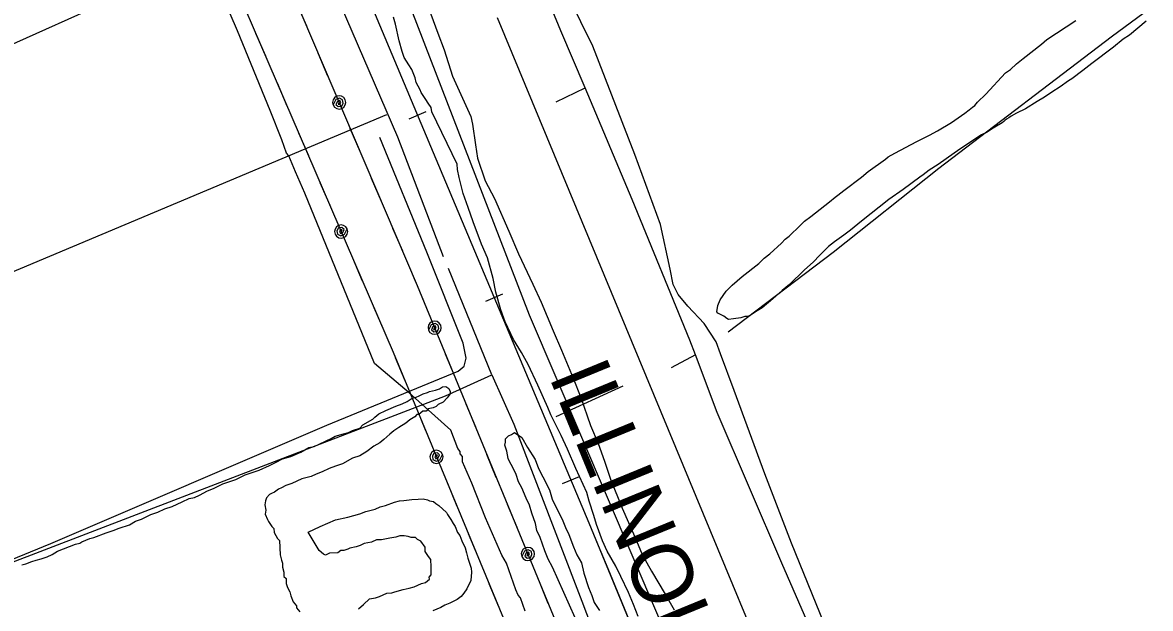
# Model space of a CAD drawing. Extents: x 3329297 to 3367176, y 649250 to 674653.
# Drawn here: x 3341368 to 3342909, y 669834 to 670634 of the extents above; entities that cross this region are included whole.
import ezdxf

# ---------------------------------------------------------------- set-up
doc = ezdxf.new("R2010")
doc.units = 0
for name, color, linetype in [('V-DTCH-CNTR', 7, 'Continuous'), ('V-RAIL-IDEN', 7, 'Continuous'), ('V-RAIL-TRAK', 7, 'Continuous'), ('V-ROAD-CNTR', 7, 'Continuous'), ('V-SITE-VEGE', 7, 'Continuous'), ('V-TOPO-SHOR', 7, 'Continuous'), ('V-UTIL-LINE', 7, 'Continuous')]:
    doc.layers.add(name, color=color, linetype=linetype)

msp = doc.modelspace()

# ---------------------------------------------------------------- linework, layer by layer
at = {"layer": 'V-DTCH-CNTR'}
for points in [[(3342681.3, 669387.6), (3342641.9, 669461.5), (3342593.9, 669531.2), (3342566.9, 669571.5), (3342550.7, 669601.8), (3342508.6, 669701.9), (3342418.3, 669923.3), (3342382, 670018), (3342340.3, 670131.6), (3342321.7, 670181.7), (3342315.5, 670198.2), (3342299.4, 670223), (3342277.1, 670246.7), (3342263.7, 670262.9), (3342256.9, 670276.2), (3342252.8, 670297.5), (3342239.4, 670358.1), (3342204.7, 670453.7), (3342147.3, 670601.7), (3342114.6, 670668.7)], [(3340890.2, 669711.6), (3341407, 669923.1), (3341783.9, 670084.3), (3341963.1, 670158.2), (3341971.5, 670164.8), (3341974.3, 670176), (3341970.3, 670196.3), (3341920.6, 670320.5), (3341856.2, 670477.1)]]:
    msp.add_lwpolyline(points, dxfattribs=at)
at = {"layer": 'V-RAIL-TRAK'}
for points in [[(3342142.3, 669950.7), (3341846.6, 670653.1)], [(3345872.4, 660898.3), (3345202.6, 662524.8), (3345202.6, 662524.8), (3343834.7, 665839), (3343834.7, 665839.1), (3342962.1, 667964.3), (3342962.1, 667964.3), (3342142.3, 669950.7), (3342142.3, 669950.7), (3341846.6, 670653.1)], [(3341896.4, 670502.6), (3341919.5, 670512.3)], [(3342001.2, 670253.8), (3342024.2, 670263.5)], [(3342105.9, 670004.9), (3342129, 670014.6)]]:
    msp.add_lwpolyline(points, dxfattribs=at)
msp.add_arc((2259538.4, 221964.1), 1171632.7, 22.3749135, 22.4799996, dxfattribs=at)
at = {"layer": 'V-ROAD-CNTR'}
msp.add_lwpolyline([(3342677.7, 669050.1), (3342017, 670640.3)], dxfattribs=at)
at = {"layer": 'V-SITE-VEGE'}
for points in [[(3341922.6, 670653.8), (3341935.4, 670619.4), (3341944.1, 670596.8), (3341955.7, 670560.6), (3341980.7, 670505.5), (3341982.9, 670495.4), (3341987, 670467.2), (3341989.5, 670448.7), (3342000.3, 670417.8), (3342012.7, 670393.6), (3342032.5, 670349.2), (3342045.7, 670318.4), (3342065.4, 670277), (3342076.6, 670252.2), (3342093.1, 670213.1), (3342104.4, 670187), (3342120.3, 670148.5), (3342130.9, 670122.4), (3342143.9, 670083.8), (3342154.4, 670059.5), (3342163.2, 670035.2), (3342171.4, 670010.8), (3342187.4, 669971.1), (3342204.5, 669932), (3342214.5, 669907.7), (3342227.4, 669885.4), (3342246.1, 669853.6), (3342258.3, 669832.4)], [(3341877.7, 670631.6), (3341874.9, 670641.1)], [(3342209.3, 669823.3), (3342202.7, 669839.9), (3342196, 669855.9), (3342185.5, 669877.7), (3342178.4, 669891.9), (3342166.7, 669912.5), (3342160.2, 669926.7), (3342152.1, 669948.7), (3342148.6, 669961.2), (3342142.4, 669980.8), (3342139, 669992.7), (3342123.9, 670025.2), (3342112.6, 670051.9), (3342104.1, 670070.2), (3342089.7, 670098.6), (3342085.7, 670108.7), (3342071.9, 670138.8), (3342058.8, 670167.2), (3342049.7, 670183.7), (3342038.8, 670201.4), (3342027.6, 670225.6), (3342021.6, 670241.6), (3342014.6, 670266), (3342010.9, 670284.6), (3342003.2, 670312.6), (3341995.2, 670331.5), (3341983.8, 670361.8), (3341977.1, 670381.4), (3341970.3, 670400.4), (3341964.6, 670422.4), (3341962.4, 670433.2), (3341962.1, 670440.4), (3341927.5, 670511.9), (3341926.6, 670517.9), (3341922.2, 670523.7), (3341919, 670529), (3341912.6, 670538.4), (3341911.3, 670542), (3341906.1, 670552), (3341904.6, 670558.6), (3341900, 670569.8), (3341896.1, 670576.3), (3341889.7, 670586.3), (3341887, 670594.6), (3341882.8, 670608.9), (3341877.7, 670631.6)], [(3342902.7, 670635.6), (3342880.1, 670616.8), (3342871.7, 670611), (3342858.1, 670600.4), (3342828.6, 670578.2), (3342816.5, 670568.4), (3342801.3, 670556.9), (3342796.8, 670554.4), (3342785.4, 670546.2), (3342774, 670538.7), (3342764.1, 670532.1), (3342754.2, 670526.2), (3342738.2, 670516.3), (3342726, 670510.4), (3342718.4, 670506.2), (3342715.3, 670503.7), (3342712.3, 670502), (3342710, 670500.4), (3342708.5, 670498.8), (3342706.2, 670497.1), (3342696.3, 670491.3), (3342694.1, 670489.6), (3342684.9, 670483.8), (3342678.1, 670480.5), (3342667.4, 670473.8), (3342659.1, 670468), (3342649.9, 670462.2), (3342640.8, 670455.6), (3342618.8, 670440), (3342606.7, 670432.5), (3342598.4, 670425.9), (3342593.8, 670422.7), (3342571.1, 670406.2), (3342551.3, 670392.2), (3342514.3, 670362.7), (3342499.2, 670350.4), (3342490.1, 670343.8), (3342477.2, 670334.8), (3342468.9, 670328.2), (3342456.9, 670316.1), (3342448.7, 670307.2), (3342435.8, 670295.8), (3342415.6, 670276.3), (3342405.8, 670268.1), (3342392.9, 670256.7), (3342378.6, 670244.5), (3342371.8, 670240.3), (3342362.6, 670234.5), (3342358.8, 670232.8), (3342354.9, 670232.7), (3342349.5, 670230.9), (3342339.4, 670229.7), (3342332.5, 670228.7), (3342330.1, 670230.1), (3342326.1, 670233.1), (3342318.1, 670237.5), (3342316.5, 670239), (3342317.7, 670247.6), (3342321.3, 670255.5), (3342329.4, 670267.5), (3342337.7, 670275.6), (3342351.3, 670287.1), (3342373.9, 670305.1), (3342381.4, 670312.4), (3342389, 670318.1), (3342404.8, 670332.8), (3342410, 670338.4), (3342415.3, 670342.5), (3342430.4, 670357.1), (3342436.4, 670362.8), (3342444.7, 670369.4), (3342470.4, 670389.1), (3342478, 670395.6), (3342481.8, 670398.1), (3342490.1, 670404.6), (3342514.3, 670422.7), (3342523.4, 670430.8), (3342546.9, 670447.3), (3342550.6, 670450.6), (3342559.8, 670455.6)], [(3342559.8, 670455.6), (3342589.6, 670471.6), (3342607.2, 670480.1), (3342617.9, 670485.9), (3342636.9, 670497.6), (3342655.1, 670510), (3342661.1, 670514.9), (3342665.7, 670518.2), (3342668.7, 670520.6), (3342672.4, 670525.4), (3342683.7, 670536), (3342710.6, 670565.1), (3342717.5, 670570), (3342725.7, 670577.4), (3342734.8, 670584.7), (3342759.8, 670604.4), (3342767.3, 670610.9), (3342806.8, 670636.6)], [(3341367.3, 669893.7), (3341372.9, 669895.3), (3341381.2, 669898.5), (3341386.8, 669900.1), (3341393.8, 669901.8), (3341402.1, 669904.9), (3341409, 669908), (3341415.9, 669912.5), (3341440.8, 669921.9), (3341446.4, 669923.5), (3341449.2, 669925), (3341460.2, 669929.7), (3341465.8, 669931.3), (3341482.5, 669937.5), (3341492.2, 669940.7), (3341500.5, 669943.9), (3341514.4, 669948.6), (3341522.7, 669953.2), (3341531, 669956.3), (3341543.4, 669962.4), (3341553.2, 669965.6), (3341562.8, 669970.2), (3341572.6, 669973.4), (3341586.4, 669979.6), (3341596.1, 669984.2), (3341603, 669985.8), (3341610, 669988.9), (3341621, 669995), (3341629.3, 669998.1), (3341641.7, 670004.2), (3341651.5, 670007.4), (3341659.8, 670010.5), (3341672.2, 670016.7), (3341682, 670019.8), (3341691.7, 670023), (3341705.5, 670029.2), (3341713.8, 670033.7), (3341723.5, 670038.3), (3341734.6, 670041.6), (3341748.4, 670047.7), (3341759.5, 670053.8), (3341766.4, 670055.5), (3341773.4, 670058.6), (3341783, 670063.2), (3341789.9, 670066.2), (3341795.5, 670069.3), (3341806.6, 670072.5), (3341813.6, 670074.2), (3341819.1, 670077.2), (3341828.8, 670080.4), (3341832.9, 670084.8), (3341846.6, 670092.4), (3341849.3, 670095.3), (3341854.8, 670099.7), (3341864.5, 670104.3), (3341878.3, 670110.5), (3341886.6, 670113.6), (3341893.6, 670116.7), (3341900.4, 670121.2), (3341906, 670122.8), (3341910.2, 670124.4), (3341915.7, 670127.4), (3341921.2, 670129), (3341924, 670130.5), (3341932.4, 670132.3), (3341937.9, 670133.9), (3341942, 670136.9), (3341946.3, 670137), (3341950.6, 670134.4), (3341952.2, 670130.2), (3341952.3, 670127.4), (3341948.3, 670121.6), (3341942.9, 670115.8)], [(3341942.9, 670115.8), (3341935.9, 670112.7), (3341933.2, 670109.8), (3341929.1, 670108.2), (3341922.1, 670106.5), (3341919.4, 670103.6), (3341915.2, 670103.4), (3341909.7, 670099), (3341906.9, 670098.9), (3341904.2, 670096), (3341897.3, 670091.5), (3341891.9, 670087.1), (3341882.3, 670081.1), (3341875.4, 670076.6), (3341869.9, 670072.1), (3341861.8, 670064.8), (3341856.3, 670060.4), (3341848.1, 670055.8), (3341838.5, 670048.4), (3341828.9, 670042.4), (3341819.1, 670039.2), (3341805.4, 670031.6), (3341795.6, 670028.5), (3341787.3, 670025.3), (3341777.6, 670020.7), (3341769.3, 670017.6), (3341762.4, 670014.5), (3341749.9, 670011.2), (3341736, 670005), (3341727.7, 670001.9), (3341722.2, 669998.9), (3341718, 669997.3), (3341712.6, 669992.9), (3341708.4, 669991.3), (3341705.6, 669989.8), (3341701.6, 669985.4), (3341700.3, 669981.1), (3341699.2, 669975.5), (3341700.8, 669968.5), (3341699.6, 669962.8), (3341702.7, 669955.9), (3341704.2, 669953.1), (3341708.7, 669946.3), (3341711.6, 669943.6), (3341711.9, 669938), (3341716.4, 669929.7), (3341719.3, 669927), (3341720.1, 669907.3), (3341721.8, 669900.3), (3341723.3, 669896.2), (3341723.5, 669890.6), (3341725.2, 669883.6), (3341725.4, 669878), (3341728.4, 669875.3), (3341728.6, 669868.2), (3341730.3, 669862.7), (3341733.3, 669857.2), (3341734.9, 669851.6), (3341738, 669843.3), (3341742.5, 669837.8), (3341742.6, 669835), (3341747, 669829.5)], [(3342123.1, 669821.5), (3342107.7, 669856.1), (3342092.3, 669890.7), (3342086.2, 669901.7), (3342081.6, 669912.8), (3342075.3, 669930.9), (3342070.7, 669940.6), (3342068.9, 669950.3), (3342064.1, 669964.2), (3342060.9, 669975.4), (3342056.3, 669985), (3342050.1, 669998.9), (3342045.6, 670007.1), (3342042.4, 670016.9), (3342037.8, 670026.5), (3342033.2, 670034.8), (3342031.7, 670039), (3342029.9, 670048.8), (3342026.8, 670057.1), (3342028, 670061.4), (3342027.8, 670065.6), (3342031.9, 670070), (3342036, 670071.5), (3342040.2, 670074.5), (3342050.3, 670067.8), (3342057.8, 670054.1), (3342068.3, 670037.6), (3342073, 670025.1), (3342079.1, 670014.1), (3342088.2, 669996.1), (3342091.5, 669983.6), (3342096.1, 669973.9), (3342105.3, 669956), (3342109.9, 669944.9), (3342114.5, 669935.2), (3342120.8, 669918.6), (3342125.4, 669907.5), (3342131.5, 669896.5), (3342134.8, 669882.5), (3342141.2, 669863.1), (3342145.9, 669852), (3342149.1, 669842.2), (3342156.5, 669831.3)], [(3341895, 669932.4), (3341889.4, 669933.6), (3341883.8, 669933.3), (3341878.2, 669931.7), (3341869.8, 669930), (3341858.6, 669928.1), (3341851.6, 669927.9), (3341844.7, 669924.8), (3341834.9, 669923), (3341829.4, 669920), (3341823.8, 669918.4), (3341815.4, 669916.6), (3341812.7, 669915.1), (3341807.1, 669913.5), (3341802.9, 669913.3), (3341798.8, 669910.4), (3341787.5, 669909.9), (3341782, 669906.9), (3341779.2, 669908.2), (3341773.3, 669913.6), (3341758.3, 669938.3), (3341774.9, 669946), (3341795.6, 669955.3), (3341812.4, 669958.7), (3341829.1, 669963.6), (3341837.4, 669966.7), (3341850, 669970), (3341856.9, 669973.1), (3341863.9, 669974.8), (3341876.3, 669979.5), (3341883.3, 669981.2), (3341888.9, 669981.4), (3341900.1, 669983.2), (3341908.6, 669983.6), (3341915.6, 669983.8), (3341921.3, 669982.6), (3341924.1, 669981.3), (3341929.8, 669980.2), (3341932.7, 669977.5), (3341937, 669974.8), (3341947.3, 669965.3), (3341948.8, 669962.6), (3341953.3, 669955.7), (3341956.3, 669950.2), (3341959.3, 669946.1), (3341962.4, 669937.8), (3341965.4, 669933.7), (3341968.5, 669926.8), (3341973, 669917.1), (3341974.7, 669910.1), (3341976.4, 669903.1), (3341979.6, 669893.4), (3341981.2, 669889.2), (3341981.4, 669883.6), (3341980.4, 669872.3), (3341975.2, 669860.9), (3341971.2, 669855.1), (3341967.2, 669850.7), (3341961.7, 669846.3), (3341952, 669841.7), (3341945.1, 669838.6), (3341939.6, 669835.6), (3341928.5, 669830.9)], [(3341918.3, 669912.2), (3341918.1, 669917.8), (3341912.2, 669926), (3341907.9, 669928.6), (3341904.9, 669931.3), (3341899.3, 669931.1), (3341895, 669932.4)], [(3341827.1, 669834), (3341833.9, 669839.9), (3341842, 669847.3), (3341850.4, 669849), (3341856, 669850.6), (3341865.7, 669855.2), (3341872.7, 669855.5), (3341876.8, 669857.1), (3341888, 669860.3), (3341896.4, 669862), (3341903.3, 669863.7), (3341913, 669868.3), (3341918.6, 669869.9), (3341924, 669874.4), (3341923.9, 669877.2), (3341926.6, 669880.1), (3341926.4, 669887.1), (3341926.2, 669891.3), (3341925.8, 669901.2), (3341922.8, 669905.3), (3341918.3, 669912.2)]]:
    msp.add_lwpolyline(points, dxfattribs=at)
at = {"layer": 'V-TOPO-SHOR'}
for p, q in [((3340278, 670120.4), (3341747.2, 670781)), ((3342097.3, 670525.9), (3342136.6, 670544.7)), ((3341025.8, 670155.5), (3341865.8, 670508.5)), ((3342287.5, 670180.5), (3342254, 670162.5)), ((3342188.1, 670137.7), (3342096.6, 670096))]:
    msp.add_line(p, q, dxfattribs=at)
for points in [[(3342332.2, 670211.6), (3342475.2, 670320.6), (3342619.6, 670435.2), (3342855.3, 670614.5), (3343080.5, 670780.8), (3343310, 670956), (3343491.2, 671086.3), (3343655.8, 671203.9), (3343697.2, 671233.5), (3343924, 671417.3), (3344230.2, 671648), (3344409.2, 671782.5), (3344486.9, 671840.9), (3344733.6, 672026.3), (3344845.9, 672104.6)], [(3342400.8, 669442.2), (3342272.5, 669740), (3342060.5, 670234.6), (3341844.7, 670793.1), (3341784.2, 670908.3), (3341727.2, 671023.5), (3341688, 671110.4), (3341661.3, 671167.1), (3341629.2, 671229.2)], [(3342414.3, 669770.5), (3342440.1, 669781.8), (3342444.8, 669785.2), (3342447.7, 669791.7), (3342443.9, 669807.4), (3342405.5, 669895.9), (3342317.2, 670101.7), (3342287.5, 670180.5), (3342279.9, 670200.6), (3342200.9, 670392.5), (3342136.6, 670544.7), (3342103.7, 670622.6), (3342044.2, 670766.5), (3341987.8, 670903), (3341888.4, 671129.2), (3341882.6, 671135.3), (3341869.2, 671131.6), (3341841.8, 671120.2)], [(3341943.2, 670314.3), (3341880.8, 670477.4), (3341795.3, 670675.9)], [(3340282.8, 670218.9), (3340223.4, 670160.2), (3340223.4, 670142.5), (3340230.5, 670131.8), (3340237.6, 670117.6), (3340248.3, 670105.2), (3340269.6, 670080.4), (3340301.6, 670046.8), (3340456.2, 669917.6), (3340529.1, 669859.1), (3340781.4, 669655.6), (3341341.6, 669892.6), (3341946.2, 670124.4), (3342009.2, 670152.9), (3341950.3, 670298.3)], [(3342009.2, 670152.9), (3342039.4, 670085.6), (3342132.2, 669844.4), (3342207.1, 669645.9), (3342223, 669631.7), (3342310.4, 669403), (3342351.4, 669300.2), (3342349.7, 669294.8), (3342344.3, 669285.9), (3342337.3, 669280.6), (3342324.8, 669280.6), (3342225.6, 669239.6)]]:
    msp.add_lwpolyline(points, dxfattribs=at)
at = {"layer": 'V-UTIL-LINE'}
for points in [[(3345932.1, 660508.5), (3345266.9, 662132.1), (3344424.6, 664170), (3343419, 666605.5), (3342586.6, 668628.9), (3341907.6, 670274.6), (3341535.6, 671146.2)], [(3341480.8, 671097), (3341874.4, 670184.1), (3342489.4, 668700.6), (3343600.8, 666004.9), (3344292.6, 664330.1), (3345012, 662588.2), (3345711.5, 660882.6)], [(3342029.3, 669896.1), (3342022.9, 669907), (3342000.8, 669957.9), (3341981.8, 670005.1), (3341969.1, 670034.2), (3341969.1, 670041.5), (3341965.9, 670045.1), (3341965.9, 670048.7), (3341962.8, 670052.4), (3341953.3, 670077.8), (3341896.4, 670128.6), (3341849, 670168.5), (3341754, 670401.1), (3341741.3, 670430.2), (3341731.8, 670452), (3341728.7, 670455.6), (3341722.3, 670473.8), (3341706.5, 670513.8), (3341662.1, 670622.8), (3341643.1, 670666.4)], [(3341756.4, 670628.9), (3341743, 670660.1)], [(3341686.6, 670619.5), (3341700.1, 670588.3)], [(3341785.4, 670560.8), (3341772.1, 670592.1)], [(3341715.9, 670551.6), (3341729.4, 670520.4)], [(3341800.7, 670524.9), (3341799.2, 670522.5), (3341801.5, 670522.6), (3341802.9, 670525), (3341801.5, 670527.5), (3341798.3, 670526.3), (3341796.4, 670522), (3341799.6, 670519.2), (3341804.4, 670519.8), (3341806.3, 670524), (3341805.5, 670528.4), (3341801.2, 670530.6), (3341796.1, 670528.7), (3341792.5, 670521.4), (3341794.4, 670518.5), (3341797.4, 670516.6), (3341800.8, 670515.9), (3341804.3, 670516.6), (3341807.2, 670518.6), (3341809.1, 670521.6), (3341809.7, 670525), (3341809, 670528.5), (3341807, 670531.4), (3341804.1, 670533.3), (3341800.6, 670533.9), (3341797.2, 670533.2), (3341794.3, 670531.2), (3341792.4, 670528.3), (3341791.7, 670524.8), (3341792.5, 670521.4)], [(3341745.2, 670483.6), (3341758.7, 670452.4)], [(3341829.4, 670457.8), (3341816, 670489.1)], [(3341774.5, 670415.7), (3341788, 670384.5)], [(3341858.4, 670389.7), (3341845.1, 670421)], [(3341803.4, 670348.6), (3341805, 670351.1), (3341802.6, 670351), (3341801.2, 670348.6), (3341802.7, 670346.1), (3341805.9, 670347.2), (3341807.7, 670351.6), (3341804.5, 670354.4), (3341799.7, 670353.8), (3341797.8, 670349.6), (3341798.7, 670345.2), (3341802.9, 670343), (3341808.1, 670344.9), (3341811.7, 670352.2), (3341809.7, 670355.1), (3341806.8, 670357), (3341803.3, 670357.6), (3341799.9, 670356.9), (3341797, 670354.9), (3341795.1, 670352), (3341794.4, 670348.5), (3341795.2, 670345.1), (3341797.2, 670342.2), (3341800.1, 670340.3), (3341803.6, 670339.6), (3341807, 670340.4), (3341809.9, 670342.4), (3341811.8, 670345.3), (3341812.4, 670348.8), (3341811.7, 670352.2)], [(3341887.5, 670321.7), (3341874.1, 670353)], [(3341818.9, 670312.8), (3341832.3, 670281.6)], [(3341916.3, 670253.5), (3341907.6, 670274.6), (3341903.2, 670284.9)], [(3341848.2, 670244.9), (3341861.6, 670213.7)], [(3341931.1, 670217.4), (3341929.6, 670215), (3341931.9, 670215.1), (3341933.3, 670217.5), (3341931.9, 670220), (3341928.7, 670218.9), (3341926.8, 670214.6), (3341930, 670211.7), (3341934.8, 670212.3), (3341936.7, 670216.4), (3341936, 670220.8), (3341931.7, 670223.1), (3341926.5, 670221.3), (3341922.8, 670214), (3341924.8, 670211.1), (3341927.7, 670209.1), (3341931.1, 670208.4), (3341934.6, 670209.1), (3341937.5, 670211.1), (3341939.5, 670214), (3341940.1, 670217.4), (3341939.5, 670220.9), (3341937.5, 670223.8), (3341934.6, 670225.8), (3341931.2, 670226.4), (3341927.7, 670225.8), (3341924.8, 670223.8), (3341922.8, 670220.9), (3341922.1, 670217.5), (3341922.8, 670214)], [(3341877.4, 670176.9), (3341890.4, 670145.5)], [(3341959, 670150), (3341946, 670181.4)], [(3341905.7, 670108.5), (3341918.7, 670077.1)], [(3341987.2, 670081.6), (3341974.2, 670113)], [(3341933.7, 670041.1), (3341935.2, 670043.5), (3341932.9, 670043.4), (3341931.5, 670041.1), (3341932.9, 670038.5), (3341936.1, 670039.7), (3341938, 670043.9), (3341934.9, 670046.8), (3341930, 670046.2), (3341928.1, 670042.1), (3341928.8, 670037.7), (3341933.1, 670035.4), (3341938.3, 670037.3), (3341942, 670044.5), (3341940, 670047.5), (3341937.1, 670049.4), (3341933.7, 670050.1), (3341930.2, 670049.4), (3341927.3, 670047.5), (3341925.3, 670044.5), (3341924.7, 670041.1), (3341925.4, 670037.6), (3341927.3, 670034.7), (3341930.2, 670032.8), (3341933.7, 670032.1), (3341937.1, 670032.8), (3341940, 670034.7), (3341942, 670037.6), (3341942.7, 670041.1), (3341942, 670044.5)], [(3342015.4, 670013.2), (3342002.5, 670044.6)], [(3341948.6, 670005.1), (3341961.6, 669973.7)], [(3342043.7, 669944.8), (3342030.7, 669976.2)], [(3341976.9, 669936.7), (3341990, 669905.3)], [(3342058.5, 669908.7), (3342057, 669906.3), (3342059.3, 669906.4), (3342060.7, 669908.7), (3342059.3, 669911.3), (3342056.1, 669910.1), (3342054.2, 669905.8), (3342057.3, 669902.9), (3342062.2, 669903.5), (3342064.1, 669907.7), (3342063.4, 669912.1), (3342059.1, 669914.3), (3342053.9, 669912.5), (3342050.2, 669905.3), (3342052.2, 669902.3), (3342055.1, 669900.4), (3342058.5, 669899.7), (3342062, 669900.4), (3342064.9, 669902.3), (3342066.9, 669905.2), (3342067.5, 669908.7), (3342066.9, 669912.1), (3342064.9, 669915), (3342062, 669917), (3342058.6, 669917.7), (3342055.1, 669917), (3342052.2, 669915.1), (3342050.2, 669912.1), (3342049.5, 669908.7), (3342050.2, 669905.3)], [(3342054.6, 669830.6), (3342048.3, 669848.8), (3342045.1, 669852.4), (3342042, 669859.7), (3342029.3, 669896.1)], [(3342005.3, 669868.3), (3342018.3, 669836.9)], [(3342086.4, 669841.2), (3342073.4, 669872.7)]]:
    msp.add_lwpolyline(points, dxfattribs=at)

# ---------------------------------------------------------------- texts
at = {"layer": 'V-RAIL-IDEN'}
msp.add_text('ILLINOIS', height=83, rotation=292.3011, dxfattribs=at).set_placement((3342086.5, 670151.6))

doc.saveas('drawing.dxf')
